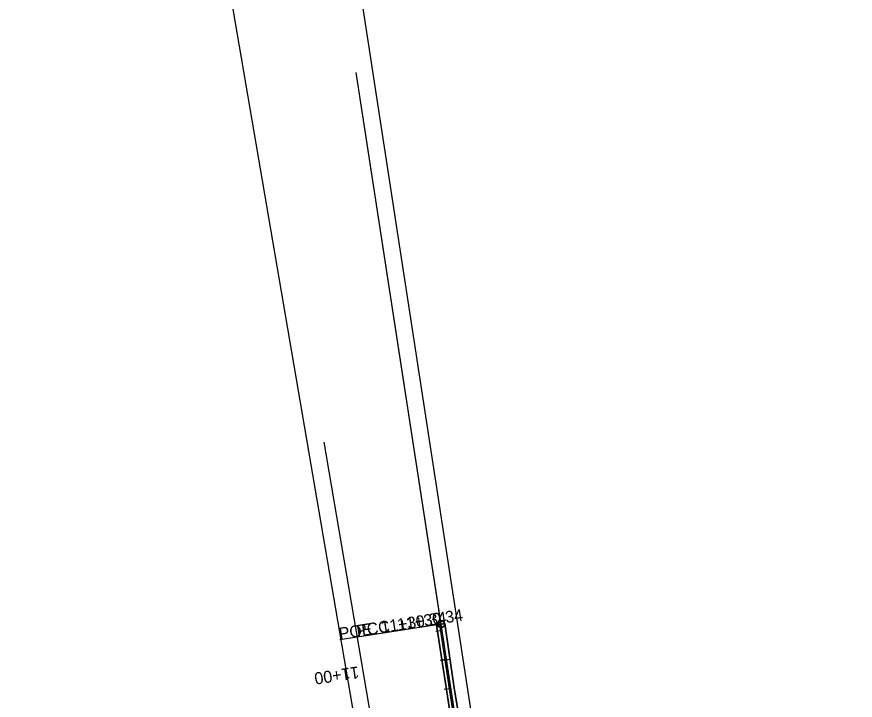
# Model space of a CAD drawing. Extents: x 11526483 to 11527252, y 9590608 to 9599499.
# Drawn here: x 11526540 to 11527252, y 9592736 to 9593317 of the extents above; entities that cross this region are included whole.
import ezdxf

# ---------------------------------------------------------------- set-up
doc = ezdxf.new("R2010")
doc.units = 0
for name, color, linetype in [('_CIVIL_CONSTRUCTION', 7, 'Continuous'), ('Alignment', 7, 'Continuous'), ('Draft_3', 7, 'Continuous'), ('EdgePaved', 7, 'Continuous'), ('Removals', 7, 'Continuous'), ('Shape', 7, 'Continuous'), ('TextAlignment', 7, 'Continuous'), ('TextAlignmentLrg', 7, 'Continuous'), ('TextAlignmentSml', 7, 'Continuous')]:
    doc.layers.add(name, color=color, linetype=linetype)

msp = doc.modelspace()

# ---------------------------------------------------------------- linework, layer by layer
at = {"layer": '_CIVIL_CONSTRUCTION'}
for p, q in [((11527252.3, 9590607.62), (11526645.05, 9594551.01)), ((11527252.3, 9590607.62), (11526645.05, 9594551.01)), ((11527165.72, 9590740.97), (11526539.81, 9594397.59)), ((11527165.72, 9590740.97), (11526539.81, 9594397.59))]:
    msp.add_line(p, q, dxfattribs=at)
at = {"layer": 'Alignment'}
msp.add_arc((11523441.22, 9592267.81), 3500, 0.004, 8.75427, dxfattribs=at)
at = {"layer": 'Draft_3'}
for p, q in [((11526912.98, 9592719.14), (11526828.29, 9593269.06)), ((11526900.45, 9592800.5), (11526828.29, 9593269.06)), ((11526891.59, 9592425.44), (11526800.92, 9592955.17))]:
    msp.add_line(p, q, dxfattribs=at)
msp.add_arc((11523441.22, 9592267.81), 3500, 0.004, 8.75427, dxfattribs=at)
at = {"layer": 'EdgePaved'}
for p in [(11526903.49, 9592800.97), (11526903.5, 9592800.97), (11526921.95, 9592634.55), (11526921.95, 9592634.55)]:
    msp.add_line(p, (11526896.49, 9592799.89), dxfattribs=at)
msp.add_lwpolyline([(11526903.5, 9592800.97), (11526911.17, 9592748.19), (11526919.76, 9592697.01), (11526927.84, 9592643.48), (11526936.04, 9592587.75), (11526944.82, 9592531.99), (11526953.7, 9592472.7), (11526962.92, 9592415.41), (11526971.47, 9592358.79), (11526980.4, 9592302.8), (11526987.6, 9592253.08), (11526996.52, 9592195.21), (11527005.28, 9592138.23), (11527013.2, 9592087.58), (11527021.66, 9592031.01), (11527030.81, 9591974.48), (11527039.32, 9591919.06), (11527047.84, 9591862.21), (11527056.56, 9591803.54), (11527065.39, 9591747.73), (11527074.67, 9591687.8)], dxfattribs=at)
at = {"layer": 'Removals'}
msp.add_lwpolyline([(11526915.27, 9592696.28), (11526907.38, 9592747.39), (11526899.23, 9592800.31), (11526903.5, 9592800.97), (11526911.17, 9592748.19), (11526919.76, 9592697.01)], dxfattribs=at)
at = {"layer": 'Shape'}
for points in [[(11526921.95, 9592634.55), (11526896.49, 9592799.89), (11526903.5, 9592800.97), (11526911.17, 9592748.19), (11526919.76, 9592697.01)], [(11526919.76, 9592697.01), (11526911.17, 9592748.19), (11526903.5, 9592800.97), (11526896.49, 9592799.89), (11526921.95, 9592634.55)]]:
    msp.add_lwpolyline(points, dxfattribs=at)
at = {"layer": 'TextAlignment'}
for q in [(11526814.46, 9592787.26), (11526829.29, 9592789.54)]:
    msp.add_line((11526900.45, 9592800.5), q, dxfattribs=at)
for radius in [3.12, 2.67]:
    msp.add_circle((11526900.45, 9592800.5), radius, dxfattribs=at)
at = {"layer": 'TextAlignmentLrg'}
msp.add_line((11526904.93, 9592770.49), (11526899.53, 9592769.71), dxfattribs=at)
at = {"layer": 'TextAlignmentSml'}
for p, q in [((11526901.26, 9592795.22), (11526895.86, 9592794.4)), ((11526904.93, 9592770.49), (11526899.53, 9592769.71)), ((11526901.91, 9592770.05), (11526907.96, 9592770.93)), ((11526908.44, 9592745.74), (11526903.03, 9592744.99))]:
    msp.add_line(p, q, dxfattribs=at)

# ---------------------------------------------------------------- texts
at = {"layer": 'TextAlignment'}
for s, p in [('11+30.34', (11526863.89, 9592795.07)), ('11+30.34', (11526849.95, 9592792.92)), ('POE ', (11526814.43, 9592787.45)), ('PCC', (11526829.26, 9592789.73))]:
    msp.add_text(s, height=10.02, rotation=8.75427, dxfattribs=at).set_placement(p)
at = {"layer": 'TextAlignmentSml'}
msp.add_text('11+00', height=10.2, rotation=188.25759, dxfattribs=at).set_placement((11526829.98, 9592764.77))

doc.saveas('drawing.dxf')
